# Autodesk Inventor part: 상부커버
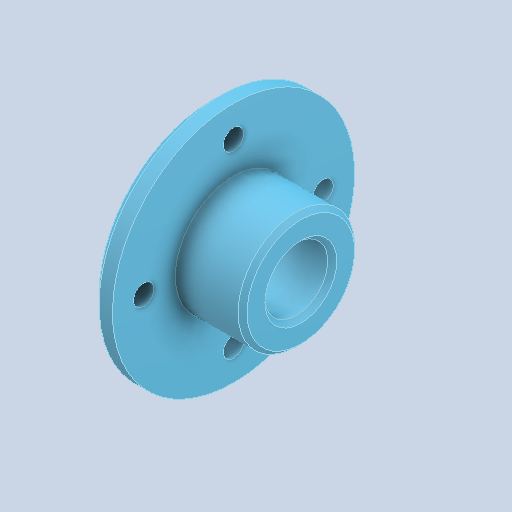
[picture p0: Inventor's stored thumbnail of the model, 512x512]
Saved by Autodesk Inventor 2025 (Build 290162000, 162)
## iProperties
Created: 2024-07
Part Number: 상부커버
Material: 알루미늄 6061
Document SubType Name: Modeling
Designer: onair
Density: 2.71 g/cm^3
Appearance: 기본값
Author: jhkim
Sending System: Autodesk Inventor 2025
Preprocessor: ST-DEVELOPER v20
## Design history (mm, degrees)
feature "솔리드1"
node "솔리드2"
